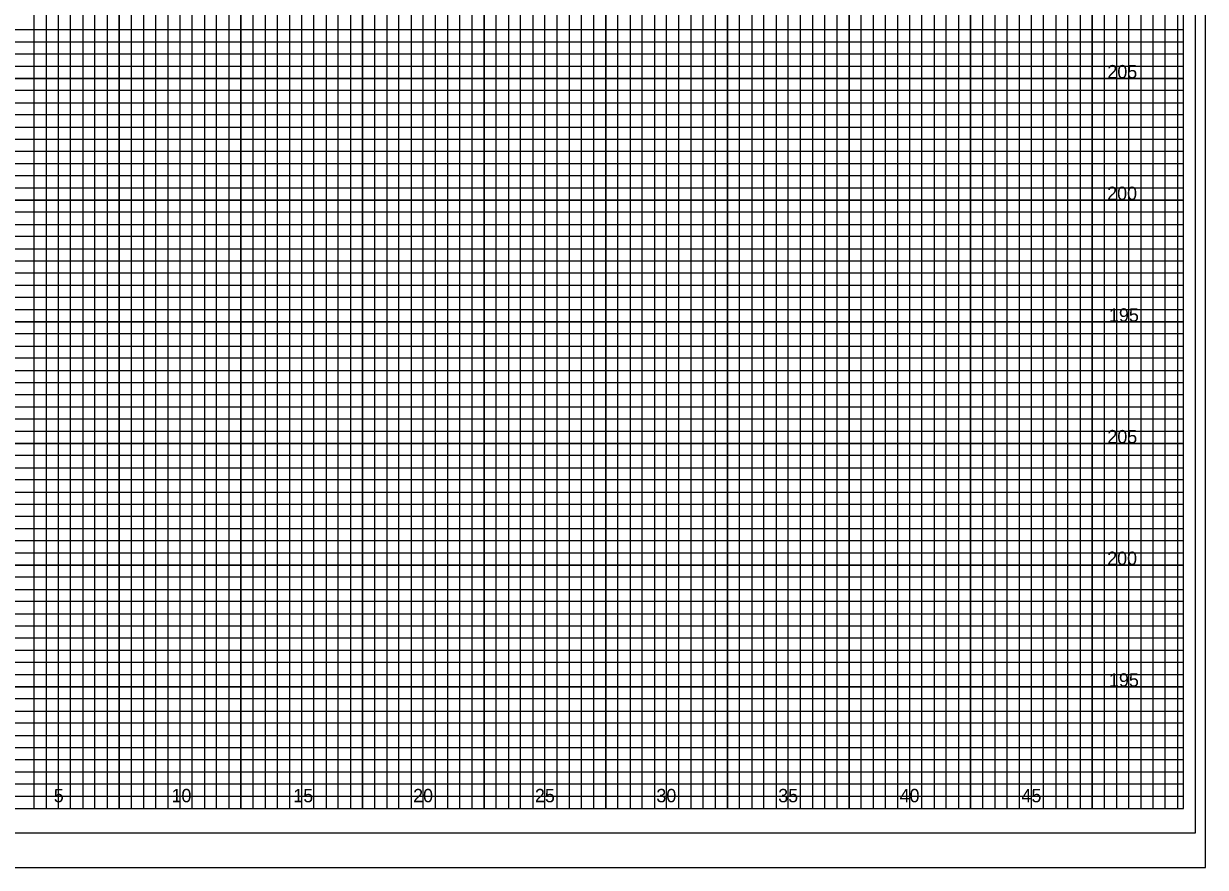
# Model space of a CAD drawing. Extents: x -4 to 103, y -2 to 351.
# Drawn here: x 54.82 to 103.4, y 68.4 to 103.08 of the extents above; entities that cross this region are included whole.
import ezdxf

# ---------------------------------------------------------------- set-up
doc = ezdxf.new("R2010")
doc.units = 0
for name, color, linetype in [('Old_Level_10', 7, 'Continuous'), ('Old_Level_16', 7, 'Continuous'), ('Old_Level_3', 7, 'Continuous'), ('Old_Level_4', 7, 'Continuous'), ('Old_Level_5', 7, 'Continuous'), ('Old_Level_6', 7, 'Continuous'), ('Old_Level_8', 7, 'Continuous'), ('Prop XS Finish Grade', 7, 'Continuous'), ('Prop XS SE Text', 7, 'Continuous')]:
    doc.layers.add(name, color=color, linetype=linetype)

msp = doc.modelspace()

# ---------------------------------------------------------------- linework, layer by layer
at = {"layer": 'Old_Level_10'}
for p, q in [((56.25, 70.825), (56.25, 135.825)), ((58.75, 70.825), (58.75, 135.825)), ((61.25, 70.825), (61.25, 135.825)), ((63.75, 70.825), (63.75, 135.825)), ((66.25, 70.825), (66.25, 135.825)), ((68.75, 70.825), (68.75, 135.825)), ((71.25, 70.825), (71.25, 135.825)), ((73.75, 70.825), (73.75, 135.825)), ((91.25, 70.825), (91.25, 134.25)), ((93.75, 70.825), (93.75, 134.25)), ((96.25, 70.825), (96.25, 134.25)), ((98.75, 70.825), (98.75, 134.25)), ((101.25, 70.825), (101.25, 134.25)), ((76.25, 70.825), (76.25, 132.825)), ((78.75, 70.825), (78.75, 132.825)), ((81.25, 70.825), (81.25, 132.825)), ((83.75, 70.825), (83.75, 132.825)), ((86.25, 70.825), (86.25, 132.825)), ((88.75, 70.825), (88.75, 132.825)), ((0, 100.825), (102.5, 100.825)), ((0, 98.325), (102.5, 98.325)), ((0, 95.825), (102.5, 95.825)), ((0, 93.325), (102.5, 93.325)), ((0, 90.825), (102.5, 90.825)), ((0, 88.325), (102.5, 88.325)), ((0, 85.825), (102.5, 85.825)), ((0, 83.325), (102.5, 83.325)), ((0, 80.825), (102.5, 80.825)), ((0, 78.325), (102.5, 78.325)), ((0, 75.825), (102.5, 75.825)), ((0, 73.325), (102.5, 73.325))]:
    msp.add_line(p, q, dxfattribs=at)
at = {"layer": 'Old_Level_3'}
msp.add_line((-3.5, 68.4), (102.1625, 68.4), dxfattribs=at)
at = {"layer": 'Old_Level_4'}
for points in [[(54.75, 70.825), (55.25, 70.825), (55.25, 135.825)], [(55.75, 135.825), (55.75, 70.825), (56.75, 70.825), (56.75, 135.825)], [(57.25, 135.825), (57.25, 70.825), (57.75, 70.825), (57.75, 135.825)], [(58.25, 135.825), (58.25, 70.825), (59.25, 70.825), (59.25, 135.825)], [(59.75, 135.825), (59.75, 70.825), (60.25, 70.825), (60.25, 135.825)], [(60.75, 135.825), (60.75, 70.825), (61.75, 70.825), (61.75, 135.825)], [(62.25, 135.825), (62.25, 70.825), (62.75, 70.825), (62.75, 135.825)], [(63.25, 135.825), (63.25, 70.825), (64.25, 70.825), (64.25, 135.825)], [(64.75, 135.825), (64.75, 70.825), (65.25, 70.825), (65.25, 135.825)], [(65.75, 135.825), (65.75, 70.825), (66.75, 70.825), (66.75, 135.825)], [(67.25, 135.825), (67.25, 70.825), (67.75, 70.825), (67.75, 135.825)], [(68.25, 135.825), (68.25, 70.825), (69.25, 70.825), (69.25, 135.825)], [(69.75, 135.825), (69.75, 70.825), (70.25, 70.825), (70.25, 135.825)], [(70.75, 135.825), (70.75, 70.825), (71.75, 70.825), (71.75, 135.825)], [(72.25, 135.825), (72.25, 70.825), (72.75, 70.825), (72.75, 135.825)], [(73.25, 135.825), (73.25, 70.825), (74.25, 70.825), (74.25, 132.825)], [(89.75, 132.825), (89.75, 70.825), (90.25, 70.825), (90.25, 134.25)], [(90.75, 134.25), (90.75, 70.825), (91.75, 70.825), (91.75, 134.25)], [(92.25, 134.25), (92.25, 70.825), (92.75, 70.825), (92.75, 134.25)], [(93.25, 134.25), (93.25, 70.825), (94.25, 70.825), (94.25, 134.25)], [(94.75, 134.25), (94.75, 70.825), (95.25, 70.825), (95.25, 134.25)], [(95.75, 134.25), (95.75, 70.825), (96.75, 70.825), (96.75, 134.25)], [(97.25, 134.25), (97.25, 70.825), (97.75, 70.825), (97.75, 134.25)], [(98.25, 134.25), (98.25, 70.825), (99.25, 70.825), (99.25, 134.25)], [(99.75, 134.25), (99.75, 70.825), (100.25, 70.825), (100.25, 134.25)], [(100.25, 134.25), (100.75, 134.25), (100.75, 70.825), (101.75, 70.825), (101.75, 134.25), (102.25, 134.25), (102.25, 70.825)], [(74.75, 132.825), (74.75, 70.825), (75.25, 70.825), (75.25, 132.825)], [(75.75, 132.825), (75.75, 70.825), (76.75, 70.825), (76.75, 132.825)], [(77.25, 132.825), (77.25, 70.825), (77.75, 70.825), (77.75, 132.825)], [(78.25, 132.825), (78.25, 70.825), (79.25, 70.825), (79.25, 132.825)], [(79.75, 132.825), (79.75, 70.825), (80.25, 70.825), (80.25, 132.825)], [(80.75, 132.825), (80.75, 70.825), (81.75, 70.825), (81.75, 132.825)], [(82.25, 132.825), (82.25, 70.825), (82.75, 70.825), (82.75, 132.825)], [(83.25, 132.825), (83.25, 70.825), (84.25, 70.825), (84.25, 132.825)], [(84.75, 132.825), (84.75, 70.825), (85.25, 70.825), (85.25, 132.825)], [(85.75, 132.825), (85.75, 70.825), (86.75, 70.825), (86.75, 132.825)], [(87.25, 132.825), (87.25, 70.825), (87.75, 70.825), (87.75, 132.825)], [(88.25, 132.825), (88.25, 70.825), (89.25, 70.825), (89.25, 132.825)], [(0, 102.325), (102.5, 102.325), (102.5, 102.825), (0, 102.825)], [(0, 101.325), (102.5, 101.325), (102.5, 101.825), (0, 101.825)], [(0, 99.825), (102.5, 99.825), (102.5, 100.325), (0, 100.325)], [(0, 98.825), (102.5, 98.825), (102.5, 99.325), (0, 99.325)], [(0, 97.325), (102.5, 97.325), (102.5, 97.825), (0, 97.825)], [(0, 96.325), (102.5, 96.325), (102.5, 96.825), (0, 96.825)], [(0, 94.825), (102.5, 94.825), (102.5, 95.325), (0, 95.325)], [(0, 93.825), (102.5, 93.825), (102.5, 94.325), (0, 94.325)], [(0, 92.325), (102.5, 92.325), (102.5, 92.825), (0, 92.825)], [(0, 91.325), (102.5, 91.325), (102.5, 91.825), (0, 91.825)], [(0, 89.825), (102.5, 89.825), (102.5, 90.325), (0, 90.325)], [(0, 88.825), (102.5, 88.825), (102.5, 89.325), (0, 89.325)], [(0, 87.325), (102.5, 87.325), (102.5, 87.825), (0, 87.825)], [(0, 86.325), (102.5, 86.325), (102.5, 86.825), (0, 86.825)], [(0, 84.825), (102.5, 84.825), (102.5, 85.325), (0, 85.325)], [(0, 83.825), (102.5, 83.825), (102.5, 84.325), (0, 84.325)], [(0, 82.325), (102.5, 82.325), (102.5, 82.825), (0, 82.825)], [(0, 81.325), (102.5, 81.325), (102.5, 81.825), (0, 81.825)], [(0, 79.825), (102.5, 79.825), (102.5, 80.325), (0, 80.325)], [(0, 78.825), (102.5, 78.825), (102.5, 79.325), (0, 79.325)], [(0, 77.325), (102.5, 77.325), (102.5, 77.825), (0, 77.825)], [(0, 76.325), (102.5, 76.325), (102.5, 76.825), (0, 76.825)], [(0, 74.825), (102.5, 74.825), (102.5, 75.325), (0, 75.325)], [(0, 73.825), (102.5, 73.825), (102.5, 74.325), (0, 74.325)], [(0, 72.325), (102.5, 72.325), (102.5, 72.825), (0, 72.825)], [(0, 71.325), (102.5, 71.325), (102.5, 71.825), (0, 71.825)]]:
    msp.add_lwpolyline(points, dxfattribs=at)
at = {"layer": 'Old_Level_5'}
msp.add_lwpolyline([(103.4, 138.225), (-3.5, 138.225), (-3.5, 68.4), (103.4, 68.4)], close=True, dxfattribs=at)
at = {"layer": 'Old_Level_6'}
msp.add_line((-3.5, 68.4), (103.4, 68.4), dxfattribs=at)
msp.add_lwpolyline([(102.5, 135.825), (0, 135.825), (0, 70.825), (102.5, 70.825)], close=True, dxfattribs=at)
at = {"layer": 'Old_Level_8'}
for points in [[(56.25, 70.825), (56.25, 135.825)], [(58.75, 135.825), (58.75, 70.825), (61.25, 70.825), (61.25, 135.825)], [(63.75, 135.825), (63.75, 70.825), (66.25, 70.825), (66.25, 135.825)], [(68.75, 135.825), (68.75, 70.825), (71.25, 70.825), (71.25, 135.825)], [(73.75, 135.825), (73.75, 70.825), (76.25, 70.825), (76.25, 132.825)], [(88.75, 132.825), (88.75, 70.825), (91.25, 70.825), (91.25, 134.25)], [(93.75, 134.25), (93.75, 70.825), (96.25, 70.825), (96.25, 134.25)], [(98.75, 134.25), (98.75, 70.825), (101.25, 70.825), (101.25, 134.25)], [(78.75, 132.825), (78.75, 70.825), (81.25, 70.825), (81.25, 132.825)], [(83.75, 132.825), (83.75, 70.825), (86.25, 70.825), (86.25, 132.825)], [(0, 98.325), (102.5, 98.325), (102.5, 100.825), (0, 100.825)], [(0, 93.325), (102.5, 93.325), (102.5, 95.825), (0, 95.825)], [(0, 88.325), (102.5, 88.325), (102.5, 90.825), (0, 90.825)], [(0, 83.325), (102.5, 83.325), (102.5, 85.825), (0, 85.825)], [(0, 78.325), (102.5, 78.325), (102.5, 80.825), (0, 80.825)], [(0, 73.325), (102.5, 73.325), (102.5, 75.825), (0, 75.825)]]:
    msp.add_lwpolyline(points, dxfattribs=at)
at = {"layer": 'Prop XS SE Text'}
msp.add_lwpolyline([(103, 136.825), (-2.8, 136.825), (-2.8, 69.825), (103, 69.825)], close=True, dxfattribs=at)

# ---------------------------------------------------------------- texts
at = {"layer": 'Old_Level_16'}
for s, p in [('5', (56.0574, 71.075)), ('10', (60.8971, 71.075)), ('15', (65.9057, 71.075)), ('20', (70.8312, 71.075)), ('25', (75.8399, 71.075)), ('30', (80.8312, 71.075)), ('35', (85.8399, 71.075)), ('40', (90.8313, 71.075)), ('45', (95.8399, 71.075))]:
    msp.add_text(s, height=0.55, dxfattribs=at).set_placement(p)
at = {"layer": 'Prop XS Finish Grade'}
for s, p in [('205', (99.3724, 100.825)), ('200', (99.3638, 95.825)), ('195', (99.4383, 90.825)), ('205', (99.3724, 85.825)), ('200', (99.3638, 80.825)), ('195', (99.4383, 75.825))]:
    msp.add_text(s, height=0.55, dxfattribs=at).set_placement(p)

doc.saveas('drawing.dxf')
